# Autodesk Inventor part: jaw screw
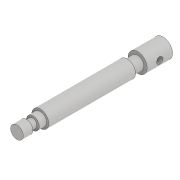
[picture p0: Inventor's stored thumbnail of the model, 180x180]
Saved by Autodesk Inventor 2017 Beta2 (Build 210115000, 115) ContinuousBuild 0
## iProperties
Created: 2016-03
Part Number: jaw screw
Material: Generic
Document SubType Name: Modeling
Designer: Sandeep
Density: 1 g/cm^3
Appearance: Default
Author: Sandeep
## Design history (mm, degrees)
sketch "Sketch1"
  geometry: L1 (0, -138)-(-6, -138); L2 (-6, -116)-(-6, -116); L3 (-6, -116)-(-8, -116); L4 (-8, -116)-(-8, -34); L5 (-8, -34)-(-6, -34); L6 (-6, -34)-(-6, -24); L7 (-6, -24)-(-9, -24); L8 (-9, -24)-(-9, 0); L9 (-9, 0)-(0, 0); L10 (0, 0)-(0, -138); L11 (0, 0)-(0, 14.581); L12 (-6, -116)-(-6, -123); L13 (-6, -123)-(-4, -123); L14 (-4, -123)-(-4, -129); L15 (-4, -129)-(-6, -129); L16 (-6, -129)-(-6, -138); 1 other entity
  constraints: 32 end point, 10 perpendicular, 3 point on line, 3 vertical, 1 coincident, 1 horizontal, 2 other
  dimensions: "d0" = 18 diameter of L8 L11; "d1" = 12 diameter of L6 L11; "d3" = 24 distance of L7.end L8.end; "d4" = 10 distance of L5.end L6.end; "d5" = 82 distance of L3.end L4.end; "d6" = 138 distance between parallel lines of L1 L9; "d8" = 16 diameter of L4 L11; "d10" = 6 distance of L13.end L14.end; "d11" = 9 distance of L15.end L1.end; "d12" = 8 diameter of L14 L11
revolve "Revolution1" sketch "Sketch1" stored, may be unused: angle "d9" = 90 deg
sketch "Sketch2"
  geometry: L1 (0, -9)-(0, 9) reference; L2 (0, 0)-(-20.975, 0); C1 r 3 at (-12, 0)
  constraints: 2 end point, 1 centre point, 1 horizontal, 1 point on line
  dimensions: "d13" = 6 diameter of C1; "d14" = 12 distance from line of L1 C1.centre
extrude "Extrusion1" cut sketch "Sketch2" distance "d15" = 25; taper "d16" = 0 deg
body "Solid1"
